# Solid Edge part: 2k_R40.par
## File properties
Author: Türk
Template: Iso Part.par
Last saved by: Türk
Revision: 9
Application: Solid Edge
Accuracy: 0,990
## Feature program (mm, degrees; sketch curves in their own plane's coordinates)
pattern "PatternOccurrence_2"  XOffset = 7.2 deg
pattern "PatternOccurrence_3"  XCount = 50; XOffset = 7.2 deg
pattern "PatternOccurrence_4"  XOffset = 12 deg
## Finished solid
Body 1: solid body, 364 faces, 1082 edges, 720 vertices.
  Faces by surface: plane 203, cylinder 161
  Edges by curve: line 760, circle 322
Bounding box of the edges (mm): 88.000 x 35.000 x 87.886, from (-44, -5, -43.9429) to (44, 30, 43.9429).
Cylindrical faces by radius (mm): R1.25 x30, R14 x1, R15 x30, R40 x50, R44 x50
Planar faces by outward normal: +y 1, -y 2, oblique 200
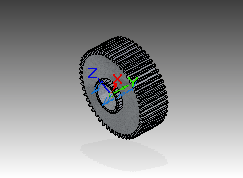
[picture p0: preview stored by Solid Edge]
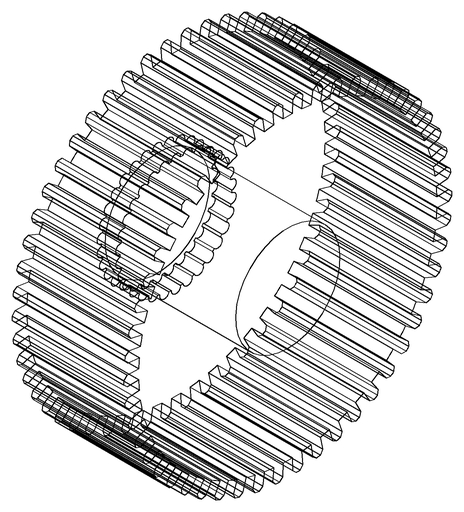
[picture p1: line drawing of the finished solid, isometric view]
